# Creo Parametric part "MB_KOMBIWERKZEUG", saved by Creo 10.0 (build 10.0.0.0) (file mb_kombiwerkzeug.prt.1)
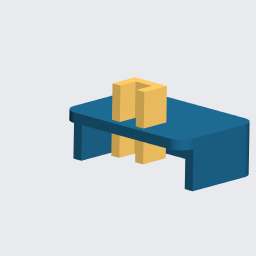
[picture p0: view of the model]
Materials in the file: S235JRG2

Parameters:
  BENENNUNG = "XXX"
  DATUM = "XX.XX.XX"
  ERSTELLER = "ARINDA"
  TEILETYP = "Fertigungsteil"
  PTC_MASTER_MATERIAL = "S235JRG2"
  SELECT_EN_NAME = "S235JRG2"
  SELECT_DIN_NAME = "RSt37-2"
  SELECT_DIN_NUMBER = "1.0038"
  SELECT_ASTM_NAME = "A 283 M Grade 2"
  MATERIAL_GROUP = "ME_ST_Baustahl"
  STANDARD_EN_DELIVERYSPEC = "DIN EN 10025"
  STANDARD_DIN_DELIVERYSPEC = "DIN 17100"

Other parameters: MASSE

Created from: KURVENAUSWAHL.PRT

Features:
  1. coordinate system
  2. datum plane "T_RECHTS_Y-Z"
  3. datum plane "T_OBEN_X-Z"
  4. datum plane "T_VORNE_X-Y"
  5. datum axis
  6. datum axis
  7. datum axis
  8. protrusion
  9. round
  10. shell "Schale 1"
  11. extrusion "Profil 2"
  12. feature "Körper Trimmen 1"
  13. feature "Körper Zusammenführen 1"

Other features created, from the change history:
  sketch "Skizze 2"
  curve "Kurve 2"
  extrusion "Profil 2"
  datum plane "DTM1" (2 times)
  sketch "Skizze 3"
  feature "Körper Trennen 1" (2 times)
  feature "Körper Zusammenführen 1" (2 times)

Other named items: T_BASIC, T_X-ACHSE, T_Y-ACHSE, T_Z-ACHSE

Layers: 00_STD-ACHSEN, 00_STD-EBENEN, 00_STD-KOORDSYS, 01_EBENEN, 01_KURVEN, KURVENELEMENTE, VOLUMENGEOMETRIE

Surfaces: 22 plane, 6 cylinder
